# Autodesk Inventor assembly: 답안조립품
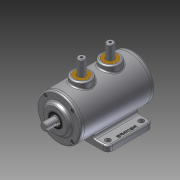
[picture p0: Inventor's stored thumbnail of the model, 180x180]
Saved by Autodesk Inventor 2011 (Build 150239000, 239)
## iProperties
Created: 2014-12
Part Number: 답안조립품
Document SubType Name: Assembly
Designer: user
Author: user
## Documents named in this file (10)
- D:\441225V1018\답안조립품.iam
- D:\441225V1018\1-본체.ipt
- D:\441225V1018\M4-소켓머리.ipt
- D:\441225V1018\오일실.ipt
- D:\441225V1018\베어링 6203.ipt
- D:\441225V1018\부시.ipt
- D:\441225V1018\슬라이더.ipt
- D:\441225V1018\4-축.ipt
- D:\441225V1018\뒷커버.ipt
- D:\441225V1018\앞커버.ipt
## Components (13 placed, 5 different names)
1. 1-본체:1 — 플러쉬:1
2. 9-M4-소켓머리:1
3. 9-M4-소켓머리:2
4. 9-M4-소켓머리:3
5. 9-M4-소켓머리:4
6. 9-M4-소켓머리:5
7. 9-M4-소켓머리:6
8. 9-M4-소켓머리:7
9. 9-M4-소켓머리:8
10. 8-오일실:1
11. 7-베어링 6203:1
12. 7-베어링 6203:2
13. 4-축:1 — 각도:1
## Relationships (2: Flush 1, Angle 1)
- 플러쉬:1 [Flush]: 1-본체:1
- 각도:1 [Angle]: 4-축:1
